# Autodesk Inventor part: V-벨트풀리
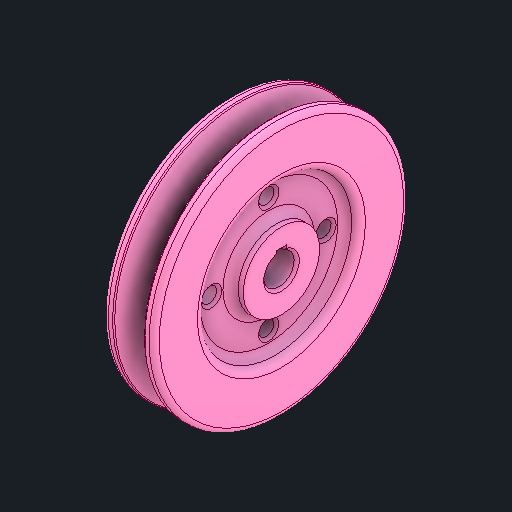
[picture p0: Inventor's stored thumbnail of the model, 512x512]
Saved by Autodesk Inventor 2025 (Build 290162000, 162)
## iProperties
Created: 2025-08
Part Number: V-벨트풀리
Material: 강철, 연강
Document SubType Name: Modeling
Designer: infra027
Density: 7.86 g/cm^3
Appearance: 기본값
Author: jhkim
Sending System: Autodesk Inventor 2026
Preprocessor: ST-DEVELOPER v20.1
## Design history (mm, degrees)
feature "솔리드1"
node "솔리드2"
